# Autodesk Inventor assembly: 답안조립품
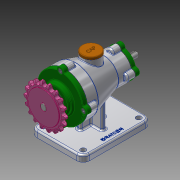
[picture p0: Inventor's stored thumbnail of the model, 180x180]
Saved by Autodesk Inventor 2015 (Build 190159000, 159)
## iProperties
Created: 2020-12
Part Number: 답안조립품
Document SubType Name: Assembly
Designer: Administrator
Author: Administrator
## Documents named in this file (15)
- C:\Users\Administrator\Desktop\701206V1020\답안조립품.iam
- C:\Users\Administrator\Desktop\701206V1020\본체.ipt
- C:\Users\Administrator\Desktop\701206V1020\개스킷 A.ipt
- C:\Users\Administrator\Desktop\701206V1020\앞커버.ipt
- C:\Users\Administrator\Desktop\701206V1020\개스킷 B.ipt
- C:\Users\Administrator\Desktop\701206V1020\뒤커버.ipt
- C:\Users\Administrator\Desktop\701206V1020\볼트 M5.ipt
- C:\Users\Administrator\Desktop\701206V1020\오일 실 17 30 8.ipt
- C:\Users\Administrator\Desktop\701206V1020\오일 실 10 20 7.ipt
- C:\Users\Administrator\Desktop\701206V1020\베어링 6203.ipt
- C:\Users\Administrator\Desktop\701206V1020\베어링 6200.ipt
- C:\Users\Administrator\Desktop\701206V1020\축.ipt
- C:\Users\Administrator\Desktop\701206V1020\키 4x4x14.ipt
- C:\Users\Administrator\Desktop\701206V1020\스프로킷.ipt
- C:\Users\Administrator\Desktop\701206V1020\마개.ipt
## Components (2 placed, 2 different names)
1. 개스킷 A:1
2. 개스킷 B:1
